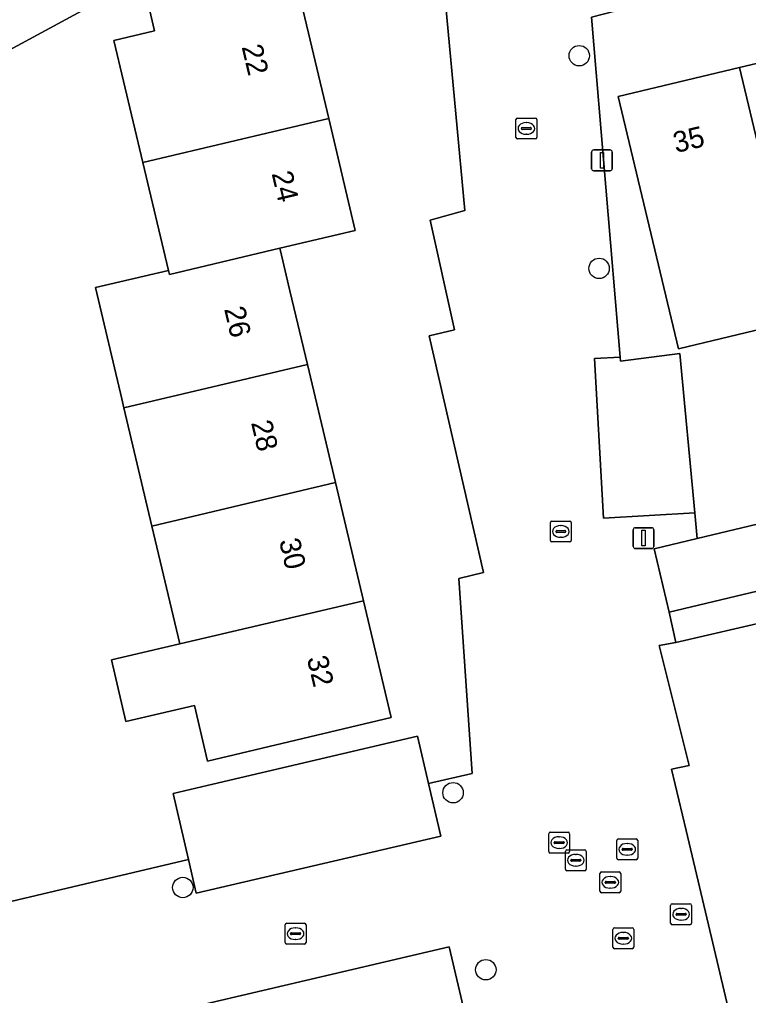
# Model space of a CAD drawing. Extents: x 158031 to 159244, y 380104 to 381214.
# Drawn here: x 158413.91 to 158448.87, y 381055.07 to 381101.88 of the extents above; entities that cross this region are included whole.
import ezdxf

# ---------------------------------------------------------------- set-up
doc = ezdxf.new("R2010")
doc.units = 0
for name, color, linetype in [('IMGEO_Berm_groen', 7, 'Continuous'), ('IMGEO_Boom', 7, 'Continuous'), ('IMGEO_Brandkraan', 7, 'Continuous'), ('IMGEO_Erf', 7, 'Continuous'), ('IMGEO_Kolk', 7, 'Continuous'), ('IMGEO_Lichtmast', 7, 'Continuous'), ('IMGEO_Muur', 7, 'Continuous'), ('IMGEO_Pand', 7, 'Continuous'), ('IMGEO_Pand_nummerreeks', 7, 'Continuous'), ('IMGEO_Parkeervlak_open', 7, 'Continuous'), ('IMGEO_Rioolput', 7, 'Continuous'), ('IMGEO_Voetpad_open', 7, 'Continuous')]:
    doc.layers.add(name, color=color, linetype=linetype)

msp = doc.modelspace()

# ---------------------------------------------------------------- linework, layer by layer
at = {"layer": 'IMGEO_Berm_groen'}
msp.add_lwpolyline([(158360.887, 381059.398), (158386.519, 381080.758), (158403.729, 381084.79), (158402.268, 381090.979), (158401.355, 381090.763), (158400.783, 381093.174), (158405.113, 381094.199), (158404.723, 381095.843), (158409.674, 381098.532), (158409.705, 381098.402), (158417.108, 381102.413), (158419.965, 381103.129), (158419.788, 381103.877), (158426.532, 381105.474), (158426.688, 381104.815), (158433.978, 381106.643), (158434.68, 381108.792), (158437.722, 381109.577), (158437.546, 381110.54), (158456.233, 381114.875)], dxfattribs=at)
at = {"layer": 'IMGEO_Boom'}
for centre in [(158440.757, 381100.142), (158441.71, 381089.941), (158434.705, 381064.795), (158421.746, 381060.248), (158436.276, 381056.306)]:
    msp.add_circle(centre, 0.489, dxfattribs=at)
at = {"layer": 'IMGEO_Brandkraan'}
for p, q in [((158445.141, 381058.539), (158445.141, 381059.391)), ((158445.216, 381059.465), (158446.068, 381059.465)), ((158446.142, 381059.391), (158446.142, 381058.539)), ((158445.4, 381058.959), (158445.4, 381058.971)), ((158445.838, 381058.922), (158445.44, 381058.922)), ((158445.443, 381059.008), (158445.841, 381059.008)), ((158445.629, 381059.245), (158445.654, 381059.245)), ((158445.884, 381058.971), (158445.884, 381058.959)), ((158446.068, 381058.465), (158445.216, 381058.465)), ((158445.652, 381058.685), (158445.627, 381058.685))]:
    msp.add_line(p, q, dxfattribs=at)
for points in [[(158445.141, 381058.539), (158445.141, 381059.391)], [(158445.216, 381059.465), (158446.068, 381059.465)], [(158446.142, 381059.391), (158446.142, 381058.539)], [(158446.068, 381058.465), (158445.216, 381058.465)]]:
    msp.add_lwpolyline(points, dxfattribs=at)
for centre, radius, start, end in [((158445.218, 381059.389), 0.0765, 91.552, 178.448), ((158445.218, 381059.389), 0.0765, 91.552, 178.448), ((158446.066, 381059.389), 0.0765, 1.552, 88.448), ((158446.066, 381059.389), 0.0765, 1.552, 88.448), ((158445.44, 381058.968), 0.0403, 85.8775, 175.7526), ((158445.437, 381058.958), 0.0366, 178.938, 274.7102), ((158445.841, 381058.965), 0.043, 264.8664, 352.4533), ((158445.845, 381058.97), 0.0386, 1.7309, 96.639), ((158445.218, 381058.541), 0.0765, 181.552, 268.448), ((158445.218, 381058.541), 0.0765, 181.552, 268.448), ((158446.066, 381058.541), 0.0765, 271.552, 358.448), ((158446.066, 381058.541), 0.0765, 271.552, 358.448)]:
    msp.add_arc(centre, radius, start, end, dxfattribs=at)
for centre, major_axis, ratio, start_param, end_param in [((158445.628, 381058.965), (-0.387, 0.002), 0.722429, 4.712389, 7.853982), ((158445.653, 381058.965), (-0.39, 0.002), 0.717154, 1.570796, 4.712389)]:
    msp.add_ellipse(centre, major_axis=major_axis, ratio=ratio, start_param=start_param, end_param=end_param, dxfattribs=at)
at = {"layer": 'IMGEO_Erf'}
for points in [[(158464.06, 381109.04), (158447.187, 381105.029), (158447.507, 381103.594), (158441.352, 381101.994), (158442.724, 381085.689), (158442.741, 381085.485), (158445.587, 381085.853), (158446.299, 381078.211), (158446.413, 381076.99), (158451.439, 381078.19)], [(158412.941, 381059.452), (158422.017, 381061.593), (158421.283, 381064.763), (158423.191, 381065.209), (158433.005, 381067.5), (158433.532, 381065.232), (158435.62, 381065.721), (158434.986, 381075.07), (158436.161, 381075.363), (158433.567, 381086.7), (158434.781, 381086.992), (158433.608, 381092.249), (158435.275, 381092.725), (158433.978, 381106.643)], [(158427.357, 381102.987), (158428.744, 381097.13), (158430.016, 381091.762), (158426.402, 381090.906), (158426.481, 381090.573), (158426.884, 381088.87), (158427.724, 381085.325), (158429.064, 381079.669), (158430.408, 381073.997), (158431.734, 381068.397), (158422.93, 381066.312), (158422.298, 381068.982), (158419.018, 381068.213), (158418.326, 381071.163), (158421.599, 381071.931), (158420.26, 381077.585), (158418.918, 381083.251), (158418.815, 381083.685), (158417.552, 381089.019), (158421.052, 381089.847), (158419.827, 381095.019), (158418.44, 381100.875), (158420.39, 381101.337), (158419.965, 381103.129)], [(158417.108, 381102.413), (158409.705, 381098.402)], [(158450.38, 381087.243), (158445.516, 381086.082), (158442.627, 381098.181), (158448.44, 381099.568), (158454.128, 381100.926)], [(158449.949, 381073.061), (158445.397, 381071.992), (158444.595, 381071.862), (158446.037, 381066.108), (158445.185, 381065.93), (158445.882, 381062.985), (158447.16, 381057.585), (158449.198, 381048.972)]]:
    msp.add_lwpolyline(points, dxfattribs=at)
at = {"layer": 'IMGEO_Kolk'}
for p, q in [((158437.72, 381096.225), (158437.72, 381097.077)), ((158437.795, 381097.151), (158438.647, 381097.151)), ((158438.208, 381096.931), (158438.233, 381096.931)), ((158438.721, 381097.077), (158438.721, 381096.225)), ((158437.979, 381096.645), (158437.979, 381096.657)), ((158438.417, 381096.608), (158438.019, 381096.608)), ((158438.022, 381096.694), (158438.42, 381096.694)), ((158438.231, 381096.371), (158438.206, 381096.371)), ((158438.463, 381096.657), (158438.463, 381096.645)), ((158438.647, 381096.151), (158437.795, 381096.151)), ((158439.373, 381076.898), (158439.373, 381077.75)), ((158439.448, 381077.824), (158440.3, 381077.824)), ((158439.861, 381077.604), (158439.886, 381077.604)), ((158440.374, 381077.75), (158440.374, 381076.898)), ((158439.632, 381077.318), (158439.632, 381077.33)), ((158440.07, 381077.281), (158439.672, 381077.281)), ((158439.675, 381077.367), (158440.073, 381077.367)), ((158439.884, 381077.044), (158439.859, 381077.044)), ((158440.116, 381077.33), (158440.116, 381077.318)), ((158440.3, 381076.824), (158439.448, 381076.824)), ((158426.653, 381057.608), (158426.653, 381058.46)), ((158426.728, 381058.534), (158427.58, 381058.534)), ((158427.654, 381058.46), (158427.654, 381057.608)), ((158426.912, 381058.028), (158426.912, 381058.04)), ((158427.35, 381057.991), (158426.952, 381057.991)), ((158426.955, 381058.077), (158427.353, 381058.077)), ((158427.141, 381058.314), (158427.166, 381058.314)), ((158427.396, 381058.04), (158427.396, 381058.028)), ((158442.37, 381057.388), (158442.37, 381058.24)), ((158442.445, 381058.314), (158443.297, 381058.314)), ((158442.672, 381057.857), (158443.07, 381057.857)), ((158442.858, 381058.094), (158442.883, 381058.094)), ((158443.371, 381058.24), (158443.371, 381057.388)), ((158427.58, 381057.534), (158426.728, 381057.534)), ((158427.164, 381057.754), (158427.139, 381057.754)), ((158442.629, 381057.808), (158442.629, 381057.82)), ((158443.067, 381057.771), (158442.669, 381057.771)), ((158442.881, 381057.534), (158442.856, 381057.534)), ((158443.113, 381057.82), (158443.113, 381057.808)), ((158443.297, 381057.314), (158442.445, 381057.314))]:
    msp.add_line(p, q, dxfattribs=at)
for points in [[(158437.72, 381096.225), (158437.72, 381097.077)], [(158437.795, 381097.151), (158438.647, 381097.151)], [(158438.721, 381097.077), (158438.721, 381096.225)], [(158438.647, 381096.151), (158437.795, 381096.151)], [(158439.373, 381076.898), (158439.373, 381077.75)], [(158439.448, 381077.824), (158440.3, 381077.824)], [(158440.374, 381077.75), (158440.374, 381076.898)], [(158440.3, 381076.824), (158439.448, 381076.824)], [(158426.653, 381057.608), (158426.653, 381058.46)], [(158426.728, 381058.534), (158427.58, 381058.534)], [(158427.654, 381058.46), (158427.654, 381057.608)], [(158442.37, 381057.388), (158442.37, 381058.24)], [(158442.445, 381058.314), (158443.297, 381058.314)], [(158443.371, 381058.24), (158443.371, 381057.388)], [(158427.58, 381057.534), (158426.728, 381057.534)], [(158443.297, 381057.314), (158442.445, 381057.314)]]:
    msp.add_lwpolyline(points, dxfattribs=at)
for centre, radius, start, end in [((158437.797, 381097.075), 0.0765, 91.552, 178.448), ((158437.797, 381097.075), 0.0765, 91.552, 178.448), ((158438.645, 381097.075), 0.0765, 1.552, 88.448), ((158438.645, 381097.075), 0.0765, 1.552, 88.448), ((158438.019, 381096.654), 0.0403, 85.8775, 175.7526), ((158438.016, 381096.644), 0.0366, 178.938, 274.7102), ((158438.42, 381096.651), 0.043, 264.8664, 352.4533), ((158438.424, 381096.656), 0.0386, 1.7309, 96.639), ((158437.797, 381096.227), 0.0765, 181.552, 268.448), ((158437.797, 381096.227), 0.0765, 181.552, 268.448), ((158438.645, 381096.227), 0.0765, 271.552, 358.448), ((158438.645, 381096.227), 0.0765, 271.552, 358.448), ((158439.45, 381077.748), 0.0765, 91.552, 178.448), ((158439.45, 381077.748), 0.0765, 91.552, 178.448), ((158440.298, 381077.748), 0.0765, 1.552, 88.448), ((158440.298, 381077.748), 0.0765, 1.552, 88.448), ((158439.672, 381077.327), 0.0403, 85.8775, 175.7526), ((158439.669, 381077.317), 0.0366, 178.938, 274.7102), ((158440.073, 381077.324), 0.043, 264.8664, 352.4533), ((158440.077, 381077.329), 0.0386, 1.7309, 96.639), ((158439.45, 381076.9), 0.0765, 181.552, 268.448), ((158439.45, 381076.9), 0.0765, 181.552, 268.448), ((158440.298, 381076.9), 0.0765, 271.552, 358.448), ((158440.298, 381076.9), 0.0765, 271.552, 358.448), ((158426.73, 381058.458), 0.0765, 91.552, 178.448), ((158426.73, 381058.458), 0.0765, 91.552, 178.448), ((158427.578, 381058.458), 0.0765, 1.552, 88.448), ((158427.578, 381058.458), 0.0765, 1.552, 88.448), ((158426.952, 381058.037), 0.0403, 85.8775, 175.7526), ((158426.949, 381058.027), 0.0366, 178.938, 274.7102), ((158427.353, 381058.034), 0.043, 264.8664, 352.4533), ((158427.357, 381058.039), 0.0386, 1.7309, 96.639), ((158442.447, 381058.238), 0.0765, 91.552, 178.448), ((158442.447, 381058.238), 0.0765, 91.552, 178.448), ((158442.669, 381057.817), 0.0403, 85.8775, 175.7526), ((158443.074, 381057.819), 0.0386, 1.7309, 96.639), ((158443.295, 381058.238), 0.0765, 1.552, 88.448), ((158443.295, 381058.238), 0.0765, 1.552, 88.448), ((158426.73, 381057.61), 0.0765, 181.552, 268.448), ((158426.73, 381057.61), 0.0765, 181.552, 268.448), ((158427.578, 381057.61), 0.0765, 271.552, 358.448), ((158427.578, 381057.61), 0.0765, 271.552, 358.448), ((158442.447, 381057.39), 0.0765, 181.552, 268.448), ((158442.447, 381057.39), 0.0765, 181.552, 268.448), ((158442.666, 381057.807), 0.0366, 178.938, 274.7102), ((158443.07, 381057.814), 0.043, 264.8664, 352.4533), ((158443.295, 381057.39), 0.0765, 271.552, 358.448), ((158443.295, 381057.39), 0.0765, 271.552, 358.448)]:
    msp.add_arc(centre, radius, start, end, dxfattribs=at)
for centre, major_axis, ratio, start_param, end_param in [((158438.207, 381096.651), (-0.387, 0.002), 0.722429, 4.712389, 7.853982), ((158438.232, 381096.651), (-0.39, 0.002), 0.717154, 1.570796, 4.712389), ((158439.86, 381077.324), (-0.387, 0.002), 0.722429, 4.712389, 7.853982), ((158439.885, 381077.324), (-0.39, 0.002), 0.717154, 1.570796, 4.712389), ((158427.14, 381058.034), (-0.387, 0.002), 0.722429, 4.712389, 7.853982), ((158427.165, 381058.034), (-0.39, 0.002), 0.717154, 1.570796, 4.712389), ((158442.857, 381057.814), (-0.387, 0.002), 0.722429, 4.712389, 7.853982), ((158442.882, 381057.814), (-0.39, 0.002), 0.717154, 1.570796, 4.712389)]:
    msp.add_ellipse(centre, major_axis=major_axis, ratio=ratio, start_param=start_param, end_param=end_param, dxfattribs=at)
at = {"layer": 'IMGEO_Lichtmast'}
for p, q in [((158441.35, 381094.72), (158441.35, 381095.52)), ((158441.35, 381095.52), (158441.35, 381094.72)), ((158441.45, 381095.62), (158442.24, 381095.62)), ((158442.24, 381095.62), (158441.45, 381095.62)), ((158442.34, 381095.52), (158442.34, 381094.72)), ((158442.34, 381094.72), (158442.34, 381095.52)), ((158442.24, 381094.62), (158441.45, 381094.62)), ((158441.45, 381094.62), (158442.24, 381094.62)), ((158443.344, 381076.604), (158443.344, 381077.404)), ((158443.344, 381077.404), (158443.344, 381076.604)), ((158443.444, 381077.504), (158444.234, 381077.504)), ((158444.234, 381077.504), (158443.444, 381077.504)), ((158444.334, 381077.404), (158444.334, 381076.604)), ((158444.334, 381076.604), (158444.334, 381077.404)), ((158444.234, 381076.504), (158443.444, 381076.504)), ((158443.444, 381076.504), (158444.234, 381076.504))]:
    msp.add_line(p, q, dxfattribs=at)
for points in [[(158441.77, 381095.495), (158441.92, 381095.495), (158441.92, 381094.745), (158441.77, 381094.745), (158441.77, 381095.495)], [(158443.764, 381077.379), (158443.914, 381077.379), (158443.914, 381076.629), (158443.764, 381076.629), (158443.764, 381077.379)]]:
    msp.add_lwpolyline(points, dxfattribs=at)
for centre, start, end in [((158441.45, 381095.52), 90, 180), ((158441.45, 381095.52), 90, 180), ((158442.24, 381095.52), 0, 90), ((158442.24, 381095.52), 360, 90), ((158441.45, 381094.72), 180, 270), ((158441.45, 381094.72), 180, 270), ((158442.24, 381094.72), 270, 0), ((158442.24, 381094.72), 270, 0), ((158443.444, 381077.404), 90, 180), ((158443.444, 381077.404), 90, 180), ((158444.234, 381077.404), 0, 90), ((158444.234, 381077.404), 360, 90), ((158443.444, 381076.604), 180, 270), ((158443.444, 381076.604), 180, 270), ((158444.234, 381076.604), 270, 0), ((158444.234, 381076.604), 270, 0)]:
    msp.add_arc(centre, 0.1, start, end, dxfattribs=at)
at = {"layer": 'IMGEO_Muur'}
msp.add_lwpolyline([(158412.941, 381059.452), (158422.017, 381061.593), (158421.283, 381064.763), (158423.191, 381065.209)], dxfattribs=at)
at = {"layer": 'IMGEO_Pand'}
for points in [[(158419.827, 381095.019), (158428.744, 381097.13), (158427.357, 381102.987), (158427.133, 381102.934), (158426.688, 381104.815), (158426.532, 381105.474), (158419.788, 381103.877), (158419.965, 381103.129), (158420.39, 381101.337), (158418.44, 381100.875)], [(158448.44, 381099.568), (158450.52, 381090.875), (158456.208, 381092.232), (158454.128, 381100.926)], [(158448.44, 381099.568), (158442.627, 381098.181), (158445.516, 381086.082), (158450.38, 381087.243), (158451.012, 381087.394), (158450.199, 381090.798), (158450.52, 381090.875)], [(158428.744, 381097.13), (158419.827, 381095.019), (158421.052, 381089.847), (158421.099, 381089.649), (158426.402, 381090.906), (158430.016, 381091.762)], [(158426.402, 381090.906), (158421.099, 381089.649), (158421.052, 381089.847), (158417.552, 381089.019), (158418.815, 381083.685), (158418.918, 381083.251), (158427.724, 381085.325), (158426.884, 381088.87), (158426.481, 381090.573)], [(158418.918, 381083.251), (158420.26, 381077.585), (158429.064, 381079.669), (158427.724, 381085.325)], [(158421.599, 381071.931), (158430.408, 381073.997), (158429.064, 381079.669), (158420.26, 381077.585)], [(158446.413, 381076.99), (158444.346, 381076.497), (158445.073, 381073.454), (158452.165, 381075.147), (158451.439, 381078.19)], [(158421.599, 381071.931), (158418.326, 381071.163), (158419.018, 381068.213), (158422.298, 381068.982), (158422.93, 381066.312), (158431.734, 381068.397), (158430.408, 381073.997)]]:
    msp.add_lwpolyline(points, close=True, dxfattribs=at)
at = {"layer": 'IMGEO_Parkeervlak_open'}
for points in [[(158445.587, 381085.853), (158442.741, 381085.485), (158442.724, 381085.689), (158441.481, 381085.619), (158441.919, 381077.961), (158446.299, 381078.211)], [(158433.532, 381065.232), (158433.005, 381067.5), (158423.191, 381065.209), (158421.283, 381064.763), (158422.017, 381061.593), (158422.391, 381059.979), (158434.119, 381062.705)], [(158435.315, 381053.994), (158434.514, 381057.407), (158421.489, 381054.349), (158397.338, 381048.68), (158397.589, 381047.573), (158388.476, 381045.507), (158389.015, 381043.132), (158389.227, 381043.184), (158389.773, 381040.782), (158398.721, 381042.793), (158398.178, 381045.087), (158403.471, 381046.341), (158408.687, 381047.577), (158408.729, 381047.587), (158411.794, 381048.313), (158413.278, 381048.683)]]:
    msp.add_lwpolyline(points, close=True, dxfattribs=at)
at = {"layer": 'IMGEO_Rioolput'}
for p, q in [((158439.295, 381061.975), (158439.295, 381062.827)), ((158439.37, 381062.901), (158440.222, 381062.901)), ((158439.783, 381062.681), (158439.808, 381062.681)), ((158440.296, 381062.827), (158440.296, 381061.975)), ((158442.635, 381062.58), (158443.487, 381062.58)), ((158439.554, 381062.395), (158439.554, 381062.407)), ((158439.992, 381062.358), (158439.594, 381062.358)), ((158439.597, 381062.444), (158439.995, 381062.444)), ((158439.806, 381062.121), (158439.781, 381062.121)), ((158440.038, 381062.407), (158440.038, 381062.395)), ((158442.56, 381061.654), (158442.56, 381062.506)), ((158442.819, 381062.074), (158442.819, 381062.086)), ((158442.862, 381062.123), (158443.26, 381062.123)), ((158443.048, 381062.36), (158443.073, 381062.36)), ((158443.303, 381062.086), (158443.303, 381062.074)), ((158443.561, 381062.506), (158443.561, 381061.654)), ((158440.222, 381061.901), (158439.37, 381061.901)), ((158440.091, 381061.13), (158440.091, 381061.982)), ((158440.166, 381062.056), (158441.018, 381062.056)), ((158440.393, 381061.599), (158440.791, 381061.599)), ((158440.579, 381061.836), (158440.604, 381061.836)), ((158441.092, 381061.982), (158441.092, 381061.13)), ((158443.257, 381062.037), (158442.859, 381062.037)), ((158443.071, 381061.8), (158443.046, 381061.8)), ((158440.35, 381061.55), (158440.35, 381061.562)), ((158440.788, 381061.513), (158440.39, 381061.513)), ((158440.602, 381061.276), (158440.577, 381061.276)), ((158440.834, 381061.562), (158440.834, 381061.55)), ((158443.487, 381061.58), (158442.635, 381061.58)), ((158441.018, 381061.056), (158440.166, 381061.056)), ((158441.746, 381060.07), (158441.746, 381060.922)), ((158441.821, 381060.996), (158442.673, 381060.996)), ((158442.234, 381060.776), (158442.259, 381060.776)), ((158442.747, 381060.922), (158442.747, 381060.07)), ((158442.005, 381060.49), (158442.005, 381060.502)), ((158442.443, 381060.453), (158442.045, 381060.453)), ((158442.048, 381060.539), (158442.446, 381060.539)), ((158442.257, 381060.216), (158442.232, 381060.216)), ((158442.489, 381060.502), (158442.489, 381060.49)), ((158442.673, 381059.996), (158441.821, 381059.996))]:
    msp.add_line(p, q, dxfattribs=at)
for points in [[(158439.295, 381061.975), (158439.295, 381062.827)], [(158439.37, 381062.901), (158440.222, 381062.901)], [(158440.296, 381062.827), (158440.296, 381061.975)], [(158442.635, 381062.58), (158443.487, 381062.58)], [(158442.56, 381061.654), (158442.56, 381062.506)], [(158443.561, 381062.506), (158443.561, 381061.654)], [(158440.222, 381061.901), (158439.37, 381061.901)], [(158440.091, 381061.13), (158440.091, 381061.982)], [(158440.166, 381062.056), (158441.018, 381062.056)], [(158441.092, 381061.982), (158441.092, 381061.13)], [(158443.487, 381061.58), (158442.635, 381061.58)], [(158441.018, 381061.056), (158440.166, 381061.056)], [(158441.746, 381060.07), (158441.746, 381060.922)], [(158441.821, 381060.996), (158442.673, 381060.996)], [(158442.747, 381060.922), (158442.747, 381060.07)], [(158442.673, 381059.996), (158441.821, 381059.996)]]:
    msp.add_lwpolyline(points, dxfattribs=at)
for centre, radius, start, end in [((158439.372, 381062.825), 0.0765, 91.552, 178.448), ((158439.372, 381062.825), 0.0765, 91.552, 178.448), ((158440.22, 381062.825), 0.0765, 1.552, 88.448), ((158440.22, 381062.825), 0.0765, 1.552, 88.448), ((158442.637, 381062.504), 0.0765, 91.552, 178.448), ((158442.637, 381062.504), 0.0765, 91.552, 178.448), ((158443.485, 381062.504), 0.0765, 1.552, 88.448), ((158443.485, 381062.504), 0.0765, 1.552, 88.448), ((158439.594, 381062.404), 0.0403, 85.8775, 175.7526), ((158439.591, 381062.394), 0.0366, 178.938, 274.7102), ((158439.995, 381062.401), 0.043, 264.8664, 352.4533), ((158439.999, 381062.406), 0.0386, 1.7309, 96.639), ((158442.859, 381062.083), 0.0403, 85.8775, 175.7526), ((158442.856, 381062.073), 0.0366, 178.938, 274.7102), ((158443.26, 381062.08), 0.043, 264.8664, 352.4533), ((158443.264, 381062.085), 0.0386, 1.7309, 96.639), ((158439.372, 381061.977), 0.0765, 181.552, 268.448), ((158439.372, 381061.977), 0.0765, 181.552, 268.448), ((158440.168, 381061.98), 0.0765, 91.552, 178.448), ((158440.168, 381061.98), 0.0765, 91.552, 178.448), ((158440.22, 381061.977), 0.0765, 271.552, 358.448), ((158440.22, 381061.977), 0.0765, 271.552, 358.448), ((158440.39, 381061.559), 0.0403, 85.8775, 175.7526), ((158440.795, 381061.561), 0.0386, 1.7309, 96.639), ((158441.016, 381061.98), 0.0765, 1.552, 88.448), ((158441.016, 381061.98), 0.0765, 1.552, 88.448), ((158442.637, 381061.656), 0.0765, 181.552, 268.448), ((158442.637, 381061.656), 0.0765, 181.552, 268.448), ((158443.485, 381061.656), 0.0765, 271.552, 358.448), ((158443.485, 381061.656), 0.0765, 271.552, 358.448), ((158440.168, 381061.132), 0.0765, 181.552, 268.448), ((158440.168, 381061.132), 0.0765, 181.552, 268.448), ((158440.387, 381061.549), 0.0366, 178.938, 274.7102), ((158440.791, 381061.556), 0.043, 264.8664, 352.4533), ((158441.016, 381061.132), 0.0765, 271.552, 358.448), ((158441.016, 381061.132), 0.0765, 271.552, 358.448), ((158441.823, 381060.92), 0.0765, 91.552, 178.448), ((158441.823, 381060.92), 0.0765, 91.552, 178.448), ((158442.671, 381060.92), 0.0765, 1.552, 88.448), ((158442.671, 381060.92), 0.0765, 1.552, 88.448), ((158442.045, 381060.499), 0.0403, 85.8775, 175.7526), ((158442.042, 381060.489), 0.0366, 178.938, 274.7102), ((158442.446, 381060.496), 0.043, 264.8664, 352.4533), ((158442.45, 381060.501), 0.0386, 1.7309, 96.639), ((158441.823, 381060.072), 0.0765, 181.552, 268.448), ((158441.823, 381060.072), 0.0765, 181.552, 268.448), ((158442.671, 381060.072), 0.0765, 271.552, 358.448), ((158442.671, 381060.072), 0.0765, 271.552, 358.448)]:
    msp.add_arc(centre, radius, start, end, dxfattribs=at)
for centre, major_axis, ratio, start_param, end_param in [((158439.782, 381062.401), (-0.387, 0.002), 0.722429, 4.712389, 7.853982), ((158439.807, 381062.401), (-0.39, 0.002), 0.717154, 1.570796, 4.712389), ((158443.047, 381062.08), (-0.387, 0.002), 0.722429, 4.712389, 7.853982), ((158443.072, 381062.08), (-0.39, 0.002), 0.717154, 1.570796, 4.712389), ((158440.578, 381061.556), (-0.387, 0.002), 0.722429, 4.712389, 7.853982), ((158440.603, 381061.556), (-0.39, 0.002), 0.717154, 1.570796, 4.712389), ((158442.233, 381060.496), (-0.387, 0.002), 0.722429, 4.712389, 7.853982), ((158442.258, 381060.496), (-0.39, 0.002), 0.717154, 1.570796, 4.712389)]:
    msp.add_ellipse(centre, major_axis=major_axis, ratio=ratio, start_param=start_param, end_param=end_param, dxfattribs=at)
at = {"layer": 'IMGEO_Voetpad_open'}
for points in [[(158456.233, 381114.875), (158437.546, 381110.54), (158437.722, 381109.577), (158434.68, 381108.792), (158433.978, 381106.643), (158435.275, 381092.725), (158433.608, 381092.249), (158434.781, 381086.992), (158433.567, 381086.7), (158436.161, 381075.363), (158434.986, 381075.07), (158435.62, 381065.721), (158433.532, 381065.232), (158434.119, 381062.705), (158422.391, 381059.979), (158422.017, 381061.593), (158412.941, 381059.452), (158409.864, 381058.723), (158410.396, 381056.477), (158402.78, 381054.674), (158387.886, 381051.146), (158387.343, 381053.48), (158383.116, 381052.496), (158374.512, 381038.654)], [(158449.198, 381048.972), (158447.16, 381057.585), (158445.882, 381062.985), (158445.185, 381065.93), (158446.037, 381066.108), (158444.595, 381071.862), (158445.397, 381071.992), (158445.073, 381073.454), (158444.346, 381076.497), (158446.413, 381076.99), (158446.299, 381078.211), (158441.919, 381077.961), (158441.481, 381085.619), (158442.724, 381085.689), (158441.352, 381101.994), (158447.507, 381103.594), (158447.187, 381105.029), (158464.06, 381109.04)], [(158452.165, 381075.147), (158445.073, 381073.454), (158445.397, 381071.992), (158449.949, 381073.061)], [(158421.489, 381054.349), (158434.514, 381057.407), (158435.315, 381053.994)]]:
    msp.add_lwpolyline(points, dxfattribs=at)

# ---------------------------------------------------------------- texts
at = {"layer": 'IMGEO_Pand_nummerreeks'}
for s, rotation, p in [('22', 283.3272, (158424.56, 381100.569)), ('35', 13.4243, (158445.394, 381095.47)), ('24', 283.3268, (158425.998, 381094.494)), ('26', 283.3268, (158423.721, 381087.997)), ('28', 283.3265, (158425.012, 381082.542)), ('30', 283.3265, (158426.354, 381076.878)), ('32', 283.3265, (158427.688, 381071.247))]:
    msp.add_text(s, height=1, rotation=rotation, dxfattribs=at).set_placement(p)

doc.saveas('drawing.dxf')
